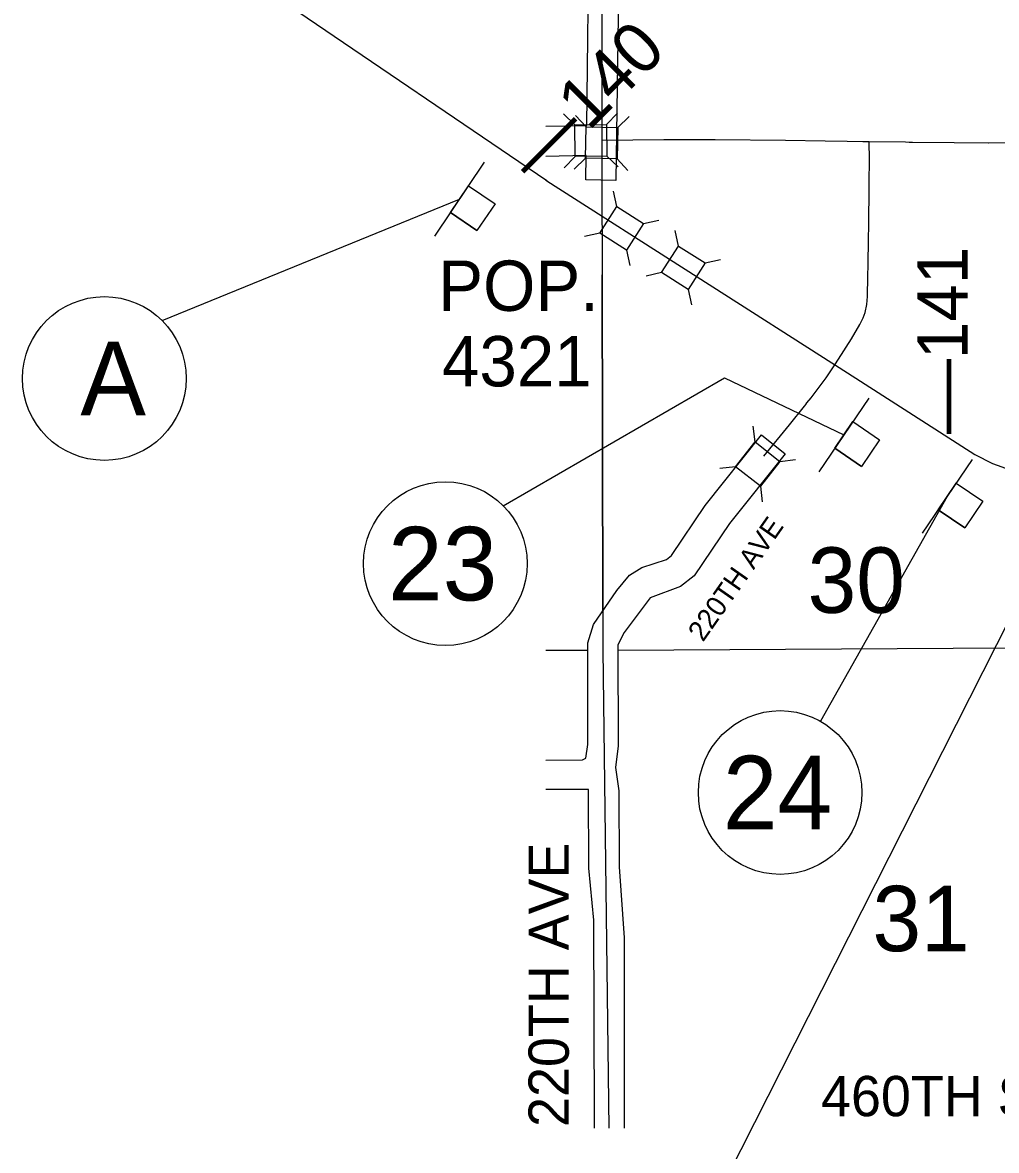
# Model space of a CAD drawing. Extents: x 10133 to 81668, y 5524 to 11018.
# Drawn here: x 18247.8 to 18489.8, y 8198.3 to 8478.4 of the extents above; entities that cross this region are included whole.
import ezdxf

# ---------------------------------------------------------------- set-up
doc = ezdxf.new("R2010")
doc.units = 0
for name, color, linetype in [('Default', 7, 'Continuous'), ('DisBoundDim', 7, 'Continuous'), ('DisCLMLOR', 7, 'Continuous'), ('DisCLMLSUR', 7, 'Continuous'), ('trf_Signal_(Temp)_Layout', 7, 'Continuous'), ('trf_SignNumber_Text', 7, 'Continuous')]:
    doc.layers.add(name, color=color, linetype=linetype)

msp = doc.modelspace()

# ---------------------------------------------------------------- linework, layer by layer
at = {"layer": 'Default'}
for p, q in [((18385.03, 8453.02), (18382.23, 8455.75)), ((18387.85, 8452.54), (18385.14, 8455.37)), ((18392.85, 8453.12), (18395.59, 8455.92)), ((18395.67, 8452.38), (18398.5, 8455.09)), ((18385.13, 8445.19), (18382.4, 8442.39)), ((18387.68, 8444.72), (18384.86, 8442.01)), ((18392.95, 8445.29), (18395.76, 8442.56)), ((18395.51, 8444.56), (18398.21, 8441.73)), ((18395.47, 8432.74), (18394.64, 8436.56)), ((18402.05, 8428.51), (18405.87, 8429.34)), ((18391.24, 8426.16), (18387.41, 8425.33)), ((18410.77, 8422.93), (18409.92, 8426.75)), ((18397.82, 8421.93), (18398.65, 8418.1)), ((18417.36, 8418.72), (18421.19, 8419.56)), ((18406.56, 8416.33), (18402.74, 8415.49)), ((18413.16, 8412.12), (18414, 8408.3)), ((18429.8, 8374.29), (18429.33, 8378.18)), ((18435.95, 8369.46), (18439.84, 8369.92)), ((18424.97, 8368.14), (18421.08, 8367.67)), ((18431.12, 8363.3), (18431.58, 8359.42))]:
    msp.add_line(p, q, dxfattribs=at)
for points in [[(18391.43, 8957.53), (18390.6, 8823.25), (18392.84, 8699.1), (18391.82, 8573.86), (18391.69, 8449.16), (18391.99, 8322.54), (18393.47, 8203.88)], [(18377.81, 8568.91), (18389.81, 8560.82), (18395.27, 8561.34), (18395.8, 8553.86), (18394.76, 8553.79), (18395.55, 8550.06), (18396.11, 8503.43), (18395.22, 8439.18), (18387.73, 8439.34), (18387.86, 8445.39), (18377.81, 8445.18)], [(18377.81, 8452.68), (18388, 8452.89), (18388.61, 8503.45), (18388.05, 8549.8), (18387.52, 8551.75), (18385.41, 8554.74), (18377.81, 8559.82)], [(18391.69, 8449.19), (18407.12, 8449.39), (18410.26, 8449.39), (18419.91, 8449.42), (18437.39, 8449.2), (18447.25, 8449.06), (18452.65, 8448.98), (18456.61, 8448.93), (18458.15, 8448.9)], [(18431.99, 8370.74), (18438.32, 8378.52), (18442.04, 8383.16), (18442.13, 8383.26), (18442.41, 8383.61), (18442.69, 8383.97), (18443.74, 8385.27), (18447.47, 8390.17), (18449.63, 8393.47), (18449.64, 8393.47), (18450.52, 8394.82), (18453.76, 8399.91), (18455.79, 8403.42), (18456.66, 8405.09), (18457.18, 8406.44), (18457.18, 8406.45), (18457.58, 8408.42), (18457.77, 8410.39), (18457.83, 8415.48), (18457.88, 8418.28), (18457.9, 8419.2), (18457.98, 8423.71), (18458.03, 8428.99), (18458.11, 8436.72), (18458.13, 8438.73), (18458.13, 8438.73), (18458.2, 8444.36), (18458.15, 8448.9)], [(18458.15, 8448.9), (18458.15, 8448.9)], [(18458.15, 8448.9), (18467.2, 8448.77), (18468.06, 8448.76), (18468.88, 8448.75), (18479.25, 8448.66), (18487.78, 8448.58), (18487.91, 8448.58), (18498.78, 8448.63), (18502.4, 8448.65), (18509.8, 8448.68), (18514.2, 8448.63), (18518.23, 8448.58)], [(18391.97, 8332.48), (18391.77, 8415.81)], [(18391.77, 8415.81), (18391.97, 8332.48)], [(18377.81, 8295.24), (18386.95, 8295.35), (18387.78, 8295.73), (18388.28, 8299.11), (18388.23, 8324.39), (18389.62, 8328.94), (18395.45, 8337.4), (18398.63, 8341.17), (18401.67, 8343.07), (18407.8, 8345.09), (18409.03, 8346.05), (18417.43, 8358.51), (18431.36, 8376.01), (18437.25, 8371.37), (18423.41, 8353.99), (18414.63, 8341.04), (18411.29, 8338.42), (18403.69, 8335.6), (18397.27, 8327), (18395.73, 8323.88), (18395.78, 8298.83), (18395.11, 8293.43), (18395.93, 8287.6), (18396.02, 8268.73), (18397.29, 8251.16), (18397.23, 8203.88)], [(18377.81, 8322.61), (18388.26, 8322.56)], [(18395.75, 8322.57), (18520.57, 8323.3)], [(18389.93, 8203.88), (18389.94, 8206.08), (18389.76, 8255.5), (18388.53, 8268.4), (18388.4, 8287.98), (18377.81, 8287.95)]]:
    msp.add_lwpolyline(points, dxfattribs=at)
for points in [[(18385.03, 8453.02), (18392.85, 8453.12), (18392.95, 8445.29), (18385.13, 8445.19)], [(18395.67, 8452.38), (18395.51, 8444.56), (18387.68, 8444.72), (18387.85, 8452.54)], [(18395.47, 8432.74), (18402.05, 8428.51), (18397.82, 8421.93), (18391.24, 8426.16)], [(18410.77, 8422.93), (18417.36, 8418.72), (18413.16, 8412.12), (18406.56, 8416.33)], [(18424.97, 8368.14), (18429.8, 8374.29), (18435.95, 8369.46), (18431.12, 8363.3)]]:
    msp.add_lwpolyline(points, close=True, dxfattribs=at)
at = {"layer": 'DisBoundDim'}
for p, q in [((18362.52, 8443.73), (18350.12, 8425.4)), ((18358.56, 8437.87), (18365.19, 8433.39)), ((18354.08, 8431.25), (18360.7, 8426.76)), ((18365.19, 8433.39), (18360.7, 8426.76)), ((18458.04, 8385.18), (18445.63, 8366.85)), ((18454.07, 8379.33), (18460.7, 8374.84)), ((18460.7, 8374.84), (18456.22, 8368.22)), ((18449.59, 8372.7), (18456.22, 8368.22)), ((18483.72, 8369.93), (18471.31, 8351.6)), ((18479.76, 8364.08), (18486.38, 8359.59)), ((18486.38, 8359.59), (18481.9, 8352.97)), ((18475.27, 8357.45), (18481.9, 8352.97))]:
    msp.add_line(p, q, dxfattribs=at)
at = {"layer": 'DisCLMLOR'}
for p, q in [((18354.08, 8431.25), (18358.56, 8437.87)), ((18354.08, 8431.25), (18358.56, 8437.87)), ((18354.08, 8431.25), (18358.56, 8437.87)), ((18354.08, 8431.25), (18358.56, 8437.87)), ((18358.56, 8437.87), (18365.19, 8433.39)), ((18358.56, 8437.87), (18365.19, 8433.39)), ((18358.56, 8437.87), (18365.19, 8433.39)), ((18358.56, 8437.87), (18365.19, 8433.39)), ((18360.7, 8426.76), (18354.08, 8431.25)), ((18360.7, 8426.76), (18354.08, 8431.25)), ((18360.7, 8426.76), (18354.08, 8431.25)), ((18360.7, 8426.76), (18354.08, 8431.25)), ((18365.19, 8433.39), (18360.7, 8426.76)), ((18365.19, 8433.39), (18360.7, 8426.76)), ((18365.19, 8433.39), (18360.7, 8426.76)), ((18365.19, 8433.39), (18360.7, 8426.76)), ((18449.59, 8372.7), (18454.07, 8379.33)), ((18449.59, 8372.7), (18454.07, 8379.33)), ((18449.59, 8372.7), (18454.07, 8379.33)), ((18449.59, 8372.7), (18454.07, 8379.33)), ((18454.07, 8379.33), (18460.7, 8374.84)), ((18454.07, 8379.33), (18460.7, 8374.84)), ((18454.07, 8379.33), (18460.7, 8374.84)), ((18454.07, 8379.33), (18460.7, 8374.84)), ((18460.7, 8374.84), (18456.22, 8368.22)), ((18460.7, 8374.84), (18456.22, 8368.22)), ((18460.7, 8374.84), (18456.22, 8368.22)), ((18460.7, 8374.84), (18456.22, 8368.22)), ((18456.22, 8368.22), (18449.59, 8372.7)), ((18456.22, 8368.22), (18449.59, 8372.7)), ((18456.22, 8368.22), (18449.59, 8372.7)), ((18456.22, 8368.22), (18449.59, 8372.7)), ((18475.27, 8357.45), (18479.76, 8364.08)), ((18475.27, 8357.45), (18479.76, 8364.08)), ((18475.27, 8357.45), (18479.76, 8364.08)), ((18475.27, 8357.45), (18479.76, 8364.08)), ((18479.76, 8364.08), (18486.38, 8359.59)), ((18479.76, 8364.08), (18486.38, 8359.59)), ((18479.76, 8364.08), (18486.38, 8359.59)), ((18479.76, 8364.08), (18486.38, 8359.59)), ((18486.38, 8359.59), (18481.9, 8352.97)), ((18486.38, 8359.59), (18481.9, 8352.97)), ((18486.38, 8359.59), (18481.9, 8352.97)), ((18486.38, 8359.59), (18481.9, 8352.97)), ((18481.9, 8352.97), (18475.27, 8357.45)), ((18481.9, 8352.97), (18475.27, 8357.45)), ((18481.9, 8352.97), (18475.27, 8357.45)), ((18481.9, 8352.97), (18475.27, 8357.45))]:
    msp.add_line(p, q, dxfattribs=at)
at = {"layer": 'DisCLMLSUR'}
for p, q in [((18282.49, 8404.41), (18356.32, 8434.56)), ((18367.21, 8358.43), (18422.16, 8390.22)), ((18422.16, 8390.22), (18451.83, 8376.02)), ((18477.52, 8360.77), (18446.02, 8304.93))]:
    msp.add_line(p, q, dxfattribs=at)
at = {"layer": 'trf_Signal_(Temp)_Layout'}
for p, q in [((18378.06, 8439.12), (18313.89, 8482.66)), ((18379.79, 8106.8), (18493.16, 8330.51))]:
    msp.add_line(p, q, dxfattribs=at)
msp.add_lwpolyline([(18377.81, 8439.26), (18378.06, 8439.12), (18452.75, 8391.47), (18484.36, 8371.19), (18488.75, 8368.94), (18493.15, 8367.35), (18497.47, 8366.26), (18501.89, 8365.65), (18526.51, 8365.29)], dxfattribs=at)
at = {"layer": 'trf_SignNumber_Text'}
for centre in [(18268.11, 8390.03), (18352.84, 8344.06), (18436.03, 8287.22)]:
    msp.add_circle(centre, 20.33, dxfattribs=at)

# ---------------------------------------------------------------- texts
at = {"layer": 'Default'}
for s, height, rotation, p in [('‒‒140', 12.5, 45, (18375.29, 8438.14)), ('‒‒141', 12.5, 90, (18482.59, 8376.26)), ('220TH AVE', 5, 55, (18416.86, 8324.43)), ('30', 16.25, 0.0072, (18442.85, 8331.84)), ('220TH AVE', 10, 90, (18383.51, 8204.18)), ('31', 16.25, 0.0072, (18458.97, 8247.81))]:
    msp.add_text(s, height=height, rotation=rotation, dxfattribs=at).set_placement(p)
for s, height, p in [('POP.', 12.5, (18351.06, 8406.83)), ('4321', 12.5, (18352.01, 8388.08)), ('460TH ST', 10, (18446.2, 8206.84))]:
    msp.add_text(s, height=height, dxfattribs=at).set_placement(p)
at = {"layer": 'trf_SignNumber_Text'}
for s, height, p in [('A', 18.26, (18262.15, 8380.9)), ('23', 18.258, (18338.6, 8334.93)), ('24', 18.258, (18421.8, 8278.09))]:
    msp.add_text(s, height=height, dxfattribs=at).set_placement(p)

doc.saveas('drawing.dxf')
